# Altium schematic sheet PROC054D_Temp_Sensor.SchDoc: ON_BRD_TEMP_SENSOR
size 558 x 431 mm; Date: Not shown in title block; ApprovedBy: Not shown in title block; CheckedBy: Not shown in title block; Author: Not shown in title block; CompanyName: Not shown in title block; DrawnBy: a0271760; Engineer: Not shown in title block; Organization: Not shown in title block; Address1: Not shown in title block; Address2: Not shown in title block; Address3: Not shown in title block; Address4: Not shown in title block; DocumentNumber: 16; Revision: Use project pAWRameter SCH_Rev; SheetNumber: 16; SheetTotal: 19; PageSetup: Record=PageOptions¦CenterHorizontal=True¦CenterVertical=True¦PrintScale=1.00¦XCorrection=1.00¦YCorrection=1.00¦PrintKind=0¦BorderSize=5000000¦LeftOffset=0¦BottomOffset=0¦Orientation=2¦PaperLength=1000¦PaperWidth=1000¦Scale=100¦PaperSource=15¦PrintQuality=600¦MediaType=1¦DitherType=10¦PaperKind=Letter¦PrintScaleMode=1
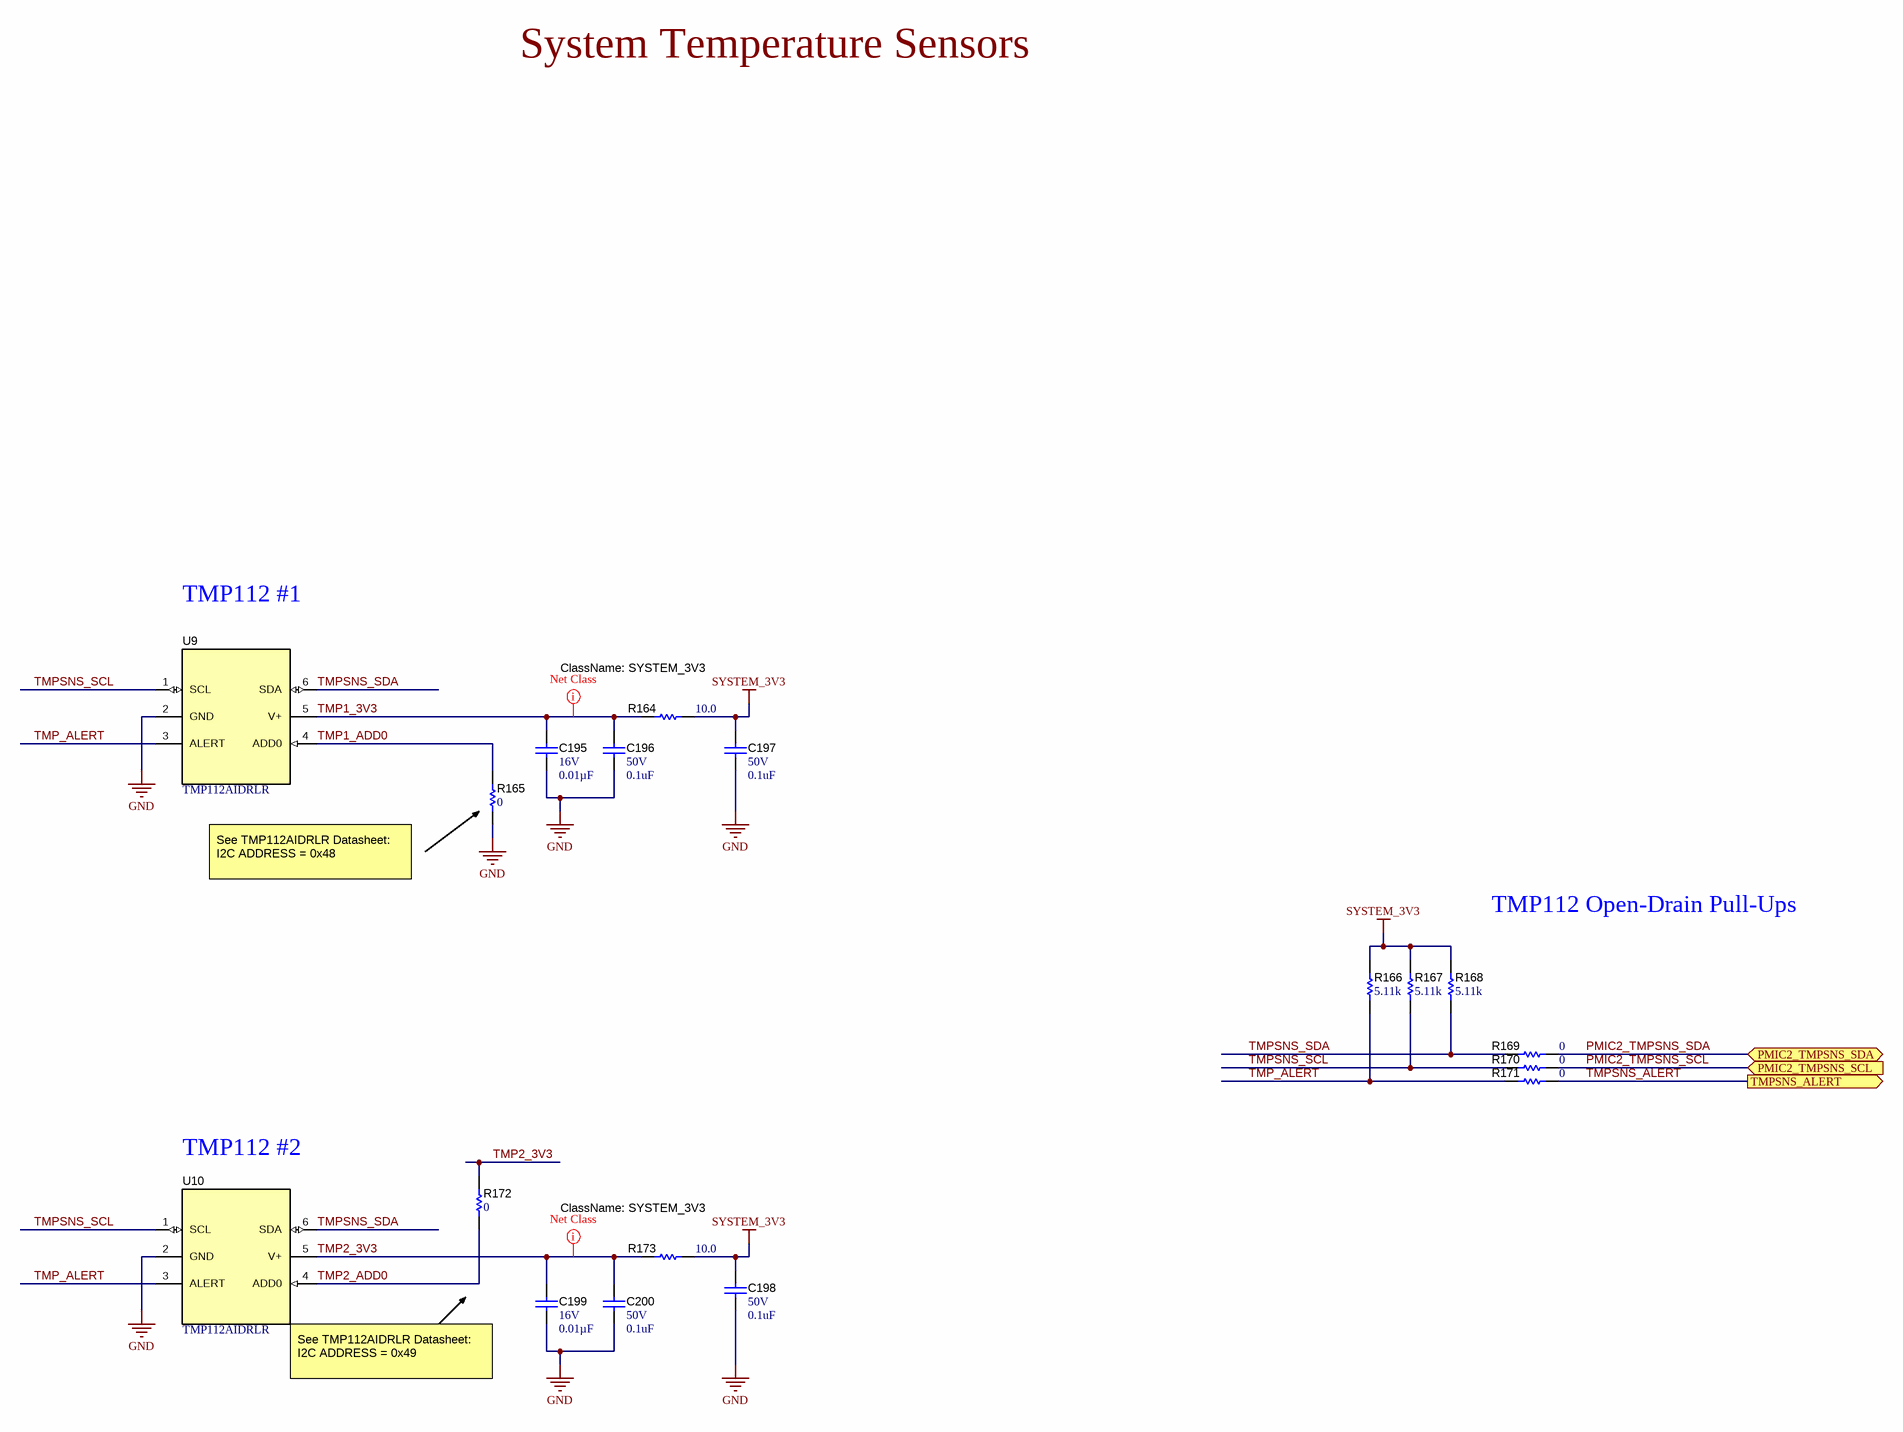
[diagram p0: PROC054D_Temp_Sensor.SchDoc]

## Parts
C195  VDC_V: 16V  ValueDisplayed: 0.01µF  [0402]  (hidden comment: C0402C103K4RACTU)
C196  VDC_V: 50V  ValueDisplayed: 0.1uF  [0402]  (hidden comment: CGA2B3X7R1H104K050BB)
C197  VDC_V: 50V  ValueDisplayed: 0.1uF  [0402]  (hidden comment: CGA2B3X7R1H104K050BB)
C198  VDC_V: 50V  ValueDisplayed: 0.1uF  [0402]  (hidden comment: CGA2B3X7R1H104K050BB)
C199  VDC_V: 16V  ValueDisplayed: 0.01µF  [0402]  (hidden comment: C0402C103K4RACTU)
C200  VDC_V: 50V  ValueDisplayed: 0.1uF  [0402]  (hidden comment: CGA2B3X7R1H104K050BB)
R164  ValueDisplayed: 10.0  [0402]  (hidden comment: CRCW040210R0FKED)
R165  ValueDisplayed: 0  [0402]  (hidden comment: ERJ-2GE0R00X)
R166  ValueDisplayed: 5.11k  [0402]  (hidden comment: CRCW04025K11FKED)
R167  ValueDisplayed: 5.11k  [0402]  (hidden comment: CRCW04025K11FKED)
R168  ValueDisplayed: 5.11k  [0402]  (hidden comment: CRCW04025K11FKED)
R169  ValueDisplayed: 0  [0402]  (hidden comment: ERJ-2GE0R00X)
R170  ValueDisplayed: 0  [0402]  (hidden comment: ERJ-2GE0R00X)
R171  ValueDisplayed: 0  [0402]  (hidden comment: ERJ-2GE0R00X)
R172  ValueDisplayed: 0  [0402]  (hidden comment: ERJ-2GE0R00X)
R173  ValueDisplayed: 10.0  [0402]  (hidden comment: CRCW040210R0FKED)
U9  TMP112AIDRLR  [DRL0006A]
U10  TMP112AIDRLR  [DRL0006A]

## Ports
PMIC2_TMPSNS_SCL (in), PMIC2_TMPSNS_SDA (bidir), TMPSNS_ALERT (out)

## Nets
GND: C195.2 C196.2 C197.2 C198.2 C199.2 C200.2 R165.1 U9.2(GND) U10.2(GND)
SYSTEM_3V3: C197.1 C198.1 R164.1 R166.2 R167.2 R168.2 R173.1
PMIC2_TMPSNS_SCL: R170.2 ; port PMIC2_TMPSNS_SCL
PMIC2_TMPSNS_SDA: R169.2 ; port PMIC2_TMPSNS_SDA
TMP1_3V3: C195.1 C196.1 R164.2 U9.5(V+)
TMP1_ADD0: R165.2 U9.4(ADD0)
TMP2_3V3: C199.1 C200.1 R172.2 R173.2 U10.5(V+)
TMP2_ADD0: R172.1 U10.4(ADD0)
TMP_ALERT: R166.1 R171.1 U9.3(ALERT) U10.3(ALERT)
TMPSNS_ALERT: R171.2 ; port TMPSNS_ALERT
TMPSNS_SCL: R167.1 R170.1 U9.1(SCL) U10.1(SCL)
TMPSNS_SDA: R168.1 R169.1 U9.6(SDA) U10.6(SDA)

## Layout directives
net class SYSTEM_3V3: TMP1_3V3, TMP2_3V3

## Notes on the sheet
- System Temperature Sensors
- TMP112 #1
- See TMP112AIDRLR Datasheet:
  I2C ADDRESS = 0x48
- TMP112 Open-Drain Pull-Ups
- TMP112 #2
- See TMP112AIDRLR Datasheet:
  I2C ADDRESS = 0x49

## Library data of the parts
C195 C199 = CMP-0078218-1: CAP, CERM, 0.01 µF, 16 V,+/- 10%, X7R, 0402; Manufacturer: Kemet; TaMin_C: -55°C; Polarized: N; Green_Lifecycle: Active; SizeAreaWB_mm2: 3; Green_REACh: Passed; U/M: EA; Value: 0.01uF; TaMax_C: 125°C; SizeZ_mm: 0.6; SizeX_mm: 1; SizeY_mm: 0.5; Cap_F: 10nF; AEC Category: Q200
C196-C198 C200 = CMP-0006325-2: CAP, CERM, 0.1 uF, 50 V, +/- 10%, X7R, AEC-Q200 Grade 1, 0402; Manufacturer: TDK; TaMin_C: -55°C; ESR_ohm: 0.039064; Polarized: N; SizeAreaWB_mm2: 3; Value1: 0.039064 ohm; U/M: EA; Value: 0.1uF; TaMax_C: 125°C; SizeZ_mm: 0.6; SizeX_mm: 1; SizeY_mm: 0.5; AEC Qualified: Y; Cap_F: 100nF; IRMS_A: 8.14669dA; AEC Category: Q200
R164 R173 = CMP-0025963-3: RES, 10.0, 1%, 0.063 W, AEC-Q200 Grade 0, 0402; Manufacturer: Vishay-Dale; Power_W: 63mW; TempCo: 100 ppm/C; Value_Code: 10R0; Value: 10.0; EIA_Code: E96; Res_ohm: 10; SizeX_mm: 1; SizeY_mm: 0.5; SizeZ_mm: 0.6; Value2: 0.063W; AEC Qualified: Y; VDC_V: 50V; AEC Category: Q200; AEC Grade: 0
R165 R172 = CMP-0026992-3: RES, 0, 5%, 0.1 W, AEC-Q200 Grade 0, 0402; Manufacturer: Panasonic; Power_W: 100mW; TempCo: 600 ppm/C; Value_Code: 0000; Value: 0; EIA_Code: E24; SizeX_mm: 1; SizeY_mm: 0.5; SizeZ_mm: 0.6; Value2: 0.1W; CompType: Resistor; AEC Qualified: Y; VDC_V: 50V; AEC Category: Q200; SizeAreaWB_mm2: 3
R166-R168 = CMP-0026463-2: RES, 5.11 k, 1%, 0.063 W, AEC-Q200 Grade 0, 0402; Manufacturer: Vishay-Dale; Power_W: 63mW; TempCo: 100 ppm/C; Value_Code: 5k11; Value: 5.11k; EIA_Code: E96; SizeX_mm: 1; SizeY_mm: 0.5; SizeZ_mm: 0.6; Value2: 0.063W; CompType: Resistor; AEC Qualified: Y; VDC_V: 50V; AEC Category: Q200; AEC Grade: 0
R169-R171 = CMP-0026992-3: RES, 0, 5%, 0.1 W, AEC-Q200 Grade 0, 0402; Manufacturer: Panasonic; Power_W: 100mW; TempCo: 600 ppm/C; Value_Code: 0000; Value: 0; EIA_Code: E24; SizeX_mm: 1; SizeY_mm: 0.5; SizeZ_mm: 0.6; Value2: 0.1W; AEC Qualified: Y; VDC_V: 50V; AEC Category: Q200; SizeAreaWB_mm2: 3
U9 U10 = CMP-0067397-2: 1.4V-Capable +/-0.5degC Temperature Sensor with Alert Function and I2C/SMBus interface in SOT-563, DRL0006A (SOT-OTHER-6); Alternate PartNumber: TMP112AIDRLT; Alternate Manufacturer: Texas Instruments; Green_Lifecycle: Active; SizeAreaWB_mm2: 6.76; Green_REACh: Passed; U/M: EA; SizeZ_mm: 0.6; SizeX_mm: 1.6; SizeArea_mm2: 2.56; CompType: IC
